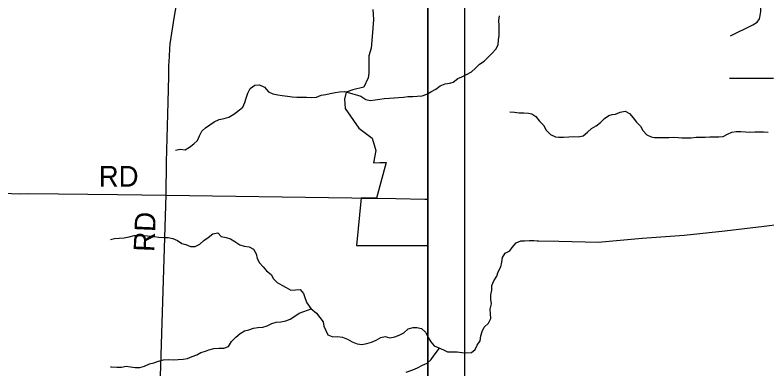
# Model space of a CAD drawing. Extents: x 0 to 34, y 0 to 22.
# Drawn here: x 12.978 to 15.045, y 4.394 to 5.366 of the extents above; entities that cross this region are included whole.
import ezdxf

# ---------------------------------------------------------------- set-up
doc = ezdxf.new("R2010")
doc.units = 0
for name, color, linetype in [('GM_X_Corporation', 7, 'Continuous'), ('GM_X_County_Road', 7, 'Continuous'), ('GM_X_County_Road_Text', 7, 'Continuous'), ('GM_X_Minor_River', 7, 'Continuous'), ('GM_X_Rail_Line', 7, 'Continuous'), ('SH_Cut_Line', 7, 'Continuous'), ('SH_Data', 7, 'Continuous')]:
    doc.layers.add(name, color=color, linetype=linetype)

msp = doc.modelspace()

# ---------------------------------------------------------------- linework, layer by layer
at = {"layer": 'GM_X_Corporation'}
msp.add_lwpolyline([(13.9616, 5.3814), (13.9633, 5.3538), (13.961, 5.3186), (13.9569, 5.2758), (13.9504, 5.2547), (13.951, 5.2354), (13.9504, 5.2066), (13.9493, 5.1937), (13.9375, 5.1679), (13.907, 5.1609), (13.8883, 5.155), (13.8836, 5.1351), (13.8859, 5.1093), (13.9234, 5.0553), (13.9598, 5.0283), (13.9703, 4.9943), (13.9633, 4.9603), (13.9809, 4.9615), (13.9985, 4.9615), (13.9718, 4.8634), (13.93, 4.8641), (13.9173, 4.7335), (14.1135, 4.7332), (14.1135, 5.8104)], dxfattribs=at)
at = {"layer": 'GM_X_County_Road'}
for p, q in [((13.3562, 3.6647), (13.3933, 4.8716)), ((13.9312, 4.8635), (13.9701, 4.8629))]:
    msp.add_line(p, q, dxfattribs=at)
for points in [[(13.3933, 4.8716), (13.395, 4.9625), (13.3993, 5.1274), (13.4007, 5.1981), (13.4014, 5.2272), (13.4026, 5.2527), (13.404, 5.2742), (13.405, 5.2873), (13.4169, 5.363), (13.4427, 5.51), (13.4888, 5.7781), (13.502, 5.8567)], [(12.8709, 4.8847), (12.873, 4.8842), (12.8851, 4.8826), (12.9078, 4.8798), (12.9276, 4.8781), (12.9482, 4.877), (12.9683, 4.8763), (12.9914, 4.8756), (13.0164, 4.8758), (13.2598, 4.873), (13.3933, 4.8716), (13.9038, 4.864)], [(13.9038, 4.864), (13.9302, 4.8636), (13.9312, 4.8635)], [(13.9701, 4.8629), (13.972, 4.8629), (14.0253, 4.862), (14.1048, 4.8606), (14.1135, 4.8603)]]:
    msp.add_lwpolyline(points, dxfattribs=at)
at = {"layer": 'GM_X_Minor_River'}
for points in [[(14.9451, 5.3093), (15.0069, 5.3397), (15.0185, 5.3467), (15.0251, 5.3561), (15.0259, 5.3595), (15.0285, 5.3761), (15.0371, 5.5569), (15.0466, 5.6613)], [(13.4193, 4.9955), (13.4326, 4.9975), (13.4463, 4.9957), (13.458, 5.0038), (13.4701, 5.0123), (13.4796, 5.0219), (13.4852, 5.0345), (13.4919, 5.0471), (13.5017, 5.0567), (13.5135, 5.0648), (13.526, 5.0728), (13.5396, 5.0794), (13.5533, 5.0822), (13.5658, 5.0857), (13.5794, 5.0938), (13.5911, 5.1023), (13.604, 5.113), (13.6103, 5.126), (13.6137, 5.1382), (13.6181, 5.152), (13.6249, 5.1646), (13.637, 5.1734), (13.6507, 5.1747), (13.6636, 5.1683), (13.6748, 5.1558), (13.687, 5.1502), (13.7003, 5.1469), (13.7129, 5.1454), (13.727, 5.1433), (13.7399, 5.1415), (13.7532, 5.1412), (13.7669, 5.1405), (13.7795, 5.1406), (13.7932, 5.1403), (13.8069, 5.1412), (13.8194, 5.1466), (13.8323, 5.1482), (13.8448, 5.1506), (13.8581, 5.1534), (13.8703, 5.1554), (13.884, 5.1563), (13.8977, 5.1529), (13.9072, 5.15), (13.9194, 5.1466), (13.9289, 5.1433), (13.9423, 5.1346), (13.9549, 5.1317), (13.9686, 5.1337), (13.9815, 5.1357), (13.9933, 5.1369), (14.0073, 5.1382), (14.0207, 5.139), (14.0328, 5.1399), (14.0457, 5.1404), (14.0583, 5.1427), (14.072, 5.1428), (14.0841, 5.1437), (14.0978, 5.1449), (14.11, 5.1492), (14.1217, 5.1554), (14.1346, 5.1631), (14.147, 5.172), (14.1607, 5.177), (14.1736, 5.179), (14.1831, 5.1821), (14.1952, 5.1921), (14.2069, 5.1968), (14.2198, 5.203), (14.2327, 5.2107), (14.244, 5.2203), (14.255, 5.2318), (14.2678, 5.2395), (14.2792, 5.251), (14.2901, 5.2614), (14.3003, 5.2725), (14.3063, 5.2843), (14.3077, 5.298), (14.3095, 5.3102), (14.309, 5.3239), (14.3093, 5.3376), (14.3084, 5.3513), (14.3098, 5.3643)], [(14.9426, 5.193), (15.0629, 5.1926)], [(14.3387, 5.1008), (14.3516, 5.0994), (14.3638, 5.0976), (14.3767, 5.0978), (14.3896, 5.0968), (14.3991, 5.0954), (14.4104, 5.0876), (14.4201, 5.0749), (14.4317, 5.0625), (14.4379, 5.0506), (14.4499, 5.0378), (14.4639, 5.0319), (14.4734, 5.0309), (14.4863, 5.031), (14.5004, 5.0319), (14.5134, 5.0324), (14.5259, 5.0322), (14.5397, 5.035), (14.552, 5.0442), (14.5629, 5.0543), (14.5756, 5.0624), (14.5875, 5.0709), (14.5991, 5.0821), (14.6103, 5.0906), (14.6199, 5.0931), (14.6294, 5.0941), (14.6421, 5.0995), (14.6555, 5.1027), (14.6672, 5.096), (14.6776, 5.084), (14.6869, 5.0725), (14.6978, 5.0608), (14.704, 5.0489), (14.7152, 5.0369), (14.7269, 5.0314), (14.7364, 5.0301), (14.749, 5.0302), (14.7623, 5.03), (14.7756, 5.0301), (14.7894, 5.031), (14.8015, 5.0304), (14.811, 5.0294), (14.8251, 5.0288), (14.8373, 5.0293), (14.8506, 5.0306), (14.8624, 5.0307), (14.8754, 5.0308), (14.888, 5.0317), (14.8994, 5.0319), (14.9127, 5.0317), (14.9249, 5.0326), (14.9368, 5.0392), (14.9484, 5.045), (14.961, 5.0463), (14.9731, 5.0461), (14.9861, 5.0455), (14.9986, 5.0445), (15.0116, 5.0457), (15.0238, 5.0459), (15.0359, 5.0457), (15.0485, 5.045)], [(14.993, 5.0437), (14.9932, 5.0437)], [(14.4134, 4.7458), (14.4728, 4.7447), (14.5817, 4.7422), (14.7025, 4.7532), (14.8173, 4.762), (14.9291, 4.7736), (15.0374, 4.786), (15.0809, 4.792)], [(13.2404, 4.7496), (13.2516, 4.7525), (13.2649, 4.7534), (13.2786, 4.7547), (13.2923, 4.757), (13.306, 4.7606), (13.3197, 4.7611), (13.3333, 4.7608), (13.36, 4.7579), (13.3737, 4.7558), (13.3874, 4.7551), (13.3996, 4.7552), (13.4121, 4.7522), (13.4247, 4.747), (13.4366, 4.7391), (13.448, 4.7358), (13.4606, 4.7301), (13.4736, 4.7302), (13.4861, 4.7372), (13.4974, 4.7468), (13.5095, 4.7556), (13.5223, 4.7653), (13.5353, 4.7676), (13.5452, 4.7578), (13.5582, 4.7552), (13.5704, 4.7515), (13.5822, 4.744), (13.596, 4.735), (13.6082, 4.7316), (13.6215, 4.7295), (13.6338, 4.7227), (13.6407, 4.7102), (13.6439, 4.6973), (13.6504, 4.6855), (13.6604, 4.6749), (13.6692, 4.6632), (13.6822, 4.6538), (13.6892, 4.642), (13.6992, 4.6315), (13.7118, 4.6239), (13.724, 4.6179), (13.7362, 4.6108), (13.7488, 4.6117), (13.7617, 4.6121), (13.7709, 4.6015), (13.776, 4.5879), (13.7806, 4.5754), (13.7915, 4.5601)], [(13.7915, 4.5597), (13.8072, 4.5468), (13.8165, 4.5352), (13.8251, 4.5236), (13.8271, 4.5114), (13.8326, 4.4995), (13.8385, 4.4873), (13.8517, 4.4821), (13.8647, 4.483), (13.8784, 4.4816), (13.892, 4.476), (13.9048, 4.4689), (13.9184, 4.4625), (13.9313, 4.4615), (13.9451, 4.4639), (13.9585, 4.4679), (13.9707, 4.4729), (13.9834, 4.4799), (13.9953, 4.4831), (14.0089, 4.4798), (14.0219, 4.4826), (14.0342, 4.4869), (14.0472, 4.4931), (14.0592, 4.5043), (14.073, 4.5075), (14.0825, 4.5077), (14.0958, 4.5055), (14.107, 4.4947), (14.1144, 4.4808), (14.1214, 4.4682), (14.1307, 4.457), (14.1557, 4.4466), (14.1674, 4.4414), (14.194, 4.4409), (14.2069, 4.4395), (14.2199, 4.4378), (14.2332, 4.4394), (14.2436, 4.4472), (14.2488, 4.4589), (14.2566, 4.4709), (14.2588, 4.4845), (14.2624, 4.497), (14.268, 4.5087), (14.28, 4.5199), (14.2859, 4.5323), (14.285, 4.5453), (14.2848, 4.5582), (14.2881, 4.5726), (14.2864, 4.5848), (14.2867, 4.5977), (14.2892, 4.6102), (14.2894, 4.6231), (14.2946, 4.6363), (14.3028, 4.6487), (14.3061, 4.6612), (14.3136, 4.6743), (14.3168, 4.6872), (14.3186, 4.7001), (14.3253, 4.7117), (14.3383, 4.7183), (14.345, 4.7281), (14.3558, 4.7401), (14.3689, 4.7459), (14.3792, 4.7461), (14.3925, 4.747), (14.4043, 4.7471), (14.4176, 4.7461)], [(13.2404, 4.3999), (13.2438, 4.3996), (13.2579, 4.399), (13.2712, 4.3987), (13.2838, 4.4014), (13.2959, 4.3996), (13.3081, 4.3982), (13.3211, 4.3979), (13.3343, 4.4014), (13.3476, 4.408), (13.3601, 4.4104), (13.373, 4.4154), (13.3859, 4.4186), (13.3989, 4.4198), (13.4129, 4.4188), (13.4266, 4.42), (13.4403, 4.4205), (13.4525, 4.4225), (13.4654, 4.4279), (13.4779, 4.433), (13.4892, 4.4392), (13.5014, 4.4431), (13.5108, 4.4462), (13.5245, 4.4505), (13.5382, 4.4513), (13.5519, 4.4511), (13.5648, 4.4557), (13.573, 4.4695), (13.5851, 4.481), (13.5972, 4.4917), (13.6089, 4.4983), (13.6207, 4.5018), (13.6336, 4.5061), (13.6454, 4.5081), (13.6591, 4.509), (13.6716, 4.5125), (13.6841, 4.519), (13.6962, 4.5222), (13.7091, 4.5238), (13.7228, 4.5258), (13.735, 4.5305), (13.7471, 4.5393), (13.7592, 4.547), (13.7717, 4.5521), (13.7922, 4.5589)], [(14.0539, 4.3854), (14.0717, 4.3919), (14.0847, 4.397), (14.0986, 4.404), (14.1109, 4.4098), (14.1221, 4.4203), (14.1307, 4.4319), (14.1452, 4.4509)]]:
    msp.add_lwpolyline(points, dxfattribs=at)
at = {"layer": 'GM_X_Rail_Line'}
msp.add_lwpolyline([(12.8629, 3.6647), (14.1135, 3.6647), (14.1135, 5.8645), (13.5036, 5.8681), (13.384, 5.8688), (13.2678, 5.8695), (12.8807, 5.8723), (12.8785, 5.5987), (12.8728, 4.8847)], close=True, dxfattribs=at)
at = {"layer": 'SH_Cut_Line'}
msp.add_lwpolyline([(8.8581, 3.6647), (14.1135, 3.6647), (14.1135, 10.4647), (8.6408, 10.4647)], dxfattribs=at)
at = {"layer": 'SH_Data'}
for p, q in [((14.2135, 10.5647), (14.2135, 3.5647)), ((14.1135, 10.4647), (14.1135, 3.6647))]:
    msp.add_line(p, q, dxfattribs=at)

# ---------------------------------------------------------------- texts
at = {"layer": 'GM_X_County_Road_Text'}
for rotation, p in [(0, (13.2081, 4.895)), (87.5313, (13.3608, 4.7148))]:
    msp.add_text('RD', height=0.05682, rotation=rotation, dxfattribs=at).set_placement(p)

doc.saveas('drawing.dxf')
